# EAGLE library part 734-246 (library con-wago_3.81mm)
Serie 734, Stiftleiste (für Leiterplatten) Einlötstift gerade 1 x 1 mm / Series 734, Male header (for PCBs) Straight solder pin 1 x 1 mm Polzahl / Pole No.: 16 Rastermaß / Pitch: 3.81 mm Bemessungsspannung / Rated Voltage: 160 V Nennstrom / Nominal Current: 10 A Lötstiftlänge: / Solder Pin Length: 4.5 mm Farbe / Color: orange / orange Stand: 01.01.2012. Die jeweils aktuellen Daten zu diesem Artikel finden Sie in unserem Produktkatalog, den Sie unter www.wago.com einsehen können. As of: 01/01/2012. Please find the newest data for this article in our product catalogue, which can be viewed under www.wago.com.
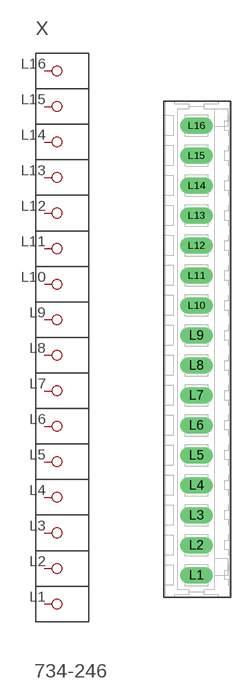
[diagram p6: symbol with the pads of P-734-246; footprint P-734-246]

Designator prefix X

## 734-246  [P-734-246]
L1  P1
L2  P2
L3  P3
L4  P4
L5  P5
L6  P6
L7  P7
L8  P8
L9  P9
L10  P10
L11  P11
L12  P12
L13  P13
L14  P14
L15  P15
L16  P16

## Footprint P-734-246 (pad centres in mm)
drill 1.4 long: L1 -0.1,-28.725; L2 -0.1,-24.915; L3 -0.1,-21.105; L4 -0.1,-17.295; L5 -0.1,-13.485; L6 -0.1,-9.675; L7 -0.1,-5.865; L8 -0.1,-2.055; L9 -0.1,1.755; L10 -0.1,5.565; L11 -0.1,9.375; L12 -0.1,13.185; L13 -0.1,16.995; L14 -0.1,20.805; L15 -0.1,24.615; L16 -0.1,28.425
